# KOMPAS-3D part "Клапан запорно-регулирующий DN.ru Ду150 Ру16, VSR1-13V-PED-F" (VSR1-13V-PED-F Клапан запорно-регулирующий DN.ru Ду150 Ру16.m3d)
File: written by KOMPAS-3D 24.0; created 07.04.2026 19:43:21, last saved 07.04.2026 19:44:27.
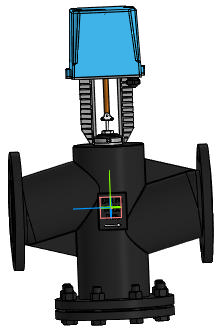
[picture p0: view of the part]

Document properties: Автор: R2D2; Полное имя файла: E:\Работа\Зайцев\Солянка\VSR1-13V-PED-F Клапан запорно-регулирующий DN.ru\DN150\VSR1-13V-PED-F Клапан запорно-регулирующий DN.ru Ду150 Ру16.m3d

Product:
- Part/product: Клапан запорно-регулирующий DN.ru Ду150 Ру16  | designation VSR1-13V-PED-F
    Масса: 56.6
    Раздел спецификации: Прочие изделия
    Примечание: D090-02896

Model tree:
1. Операция без истории:1  (labels: SHAPEOBJECT3D_ATTR_BUTT)

Expressions: VSR1-13V-PED-F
